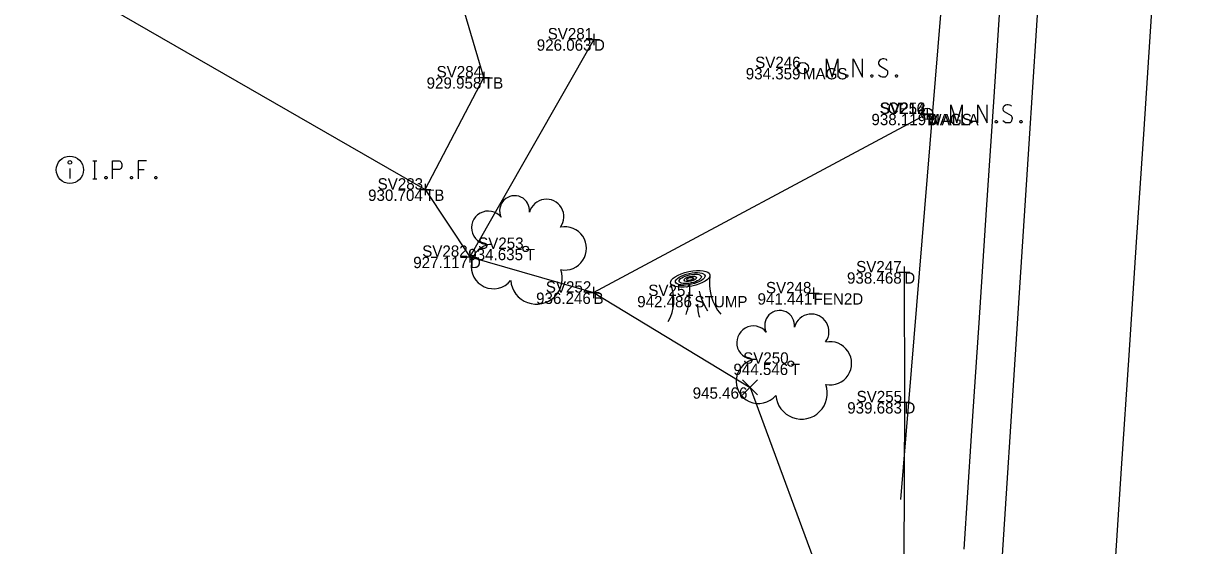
# Model space of a CAD drawing. Extents: x 1988835 to 1989144, y 657973 to 659339.
# Drawn here: x 1988889.6 to 1988993.8, y 658616.1 to 658662.1 of the extents above; entities that cross this region are included whole.
import ezdxf

# ---------------------------------------------------------------- set-up
doc = ezdxf.new("R2010")
doc.units = 0
for name, color, linetype in [('BR_X_SV_Abut_Text', 7, 'Continuous'), ('DR_X_Ditch', 7, 'Continuous'), ('DT_X_Terrain_Boundary', 7, 'Continuous'), ('PM_X_CL_Pass_Proh_Rt', 7, 'Continuous'), ('PV_X_EOP', 7, 'Continuous'), ('PV_X_Shoulder_Aggregate', 7, 'Continuous'), ('RD_X_Fence', 7, 'Continuous'), ('SV_P_Control_Cells_Set', 7, 'Continuous'), ('SV_X_Break_Lines', 7, 'Continuous'), ('SV_X_Mon_Cells_Found', 7, 'Continuous'), ('SV_X_Random_Point', 7, 'Continuous'), ('SV_X_Shot_Marker', 7, 'Continuous'), ('SV_X_Text_Comment', 7, 'Continuous'), ('SV_X_Top_of_Bank', 7, 'Continuous'), ('UT_X_Telecom', 7, 'Continuous'), ('UT_X_Telecom_Cells', 7, 'Continuous'), ('VG_X_Cells', 7, 'Continuous')]:
    doc.layers.add(name, color=color, linetype=linetype)

msp = doc.modelspace()

# ---------------------------------------------------------------- linework, layer by layer
at = {"layer": 'DR_X_Ditch'}
for points in [[(1988939.96, 658660.7), (1988929, 658641.52)], [(1988967.37, 658640.15), (1988967.38, 658628.69), (1988967.24, 658593.53)]]:
    msp.add_lwpolyline(points, dxfattribs=at)
at = {"layer": 'DT_X_Terrain_Boundary'}
msp.add_lwpolyline([(1988987.83, 658845.23), (1988984.81, 658799.59), (1988977.84, 658799.78), (1988968.83, 658798.91), (1988942.79, 658792.82), (1988927.35, 658779.11), (1988913.54, 658771.15), (1988908.13, 658758.46), (1988901.04, 658731.18), (1988897.02, 658728.69), (1988894.52, 658726.61), (1988891.03, 658722.22), (1988888.81, 658718.86), (1988886.03, 658711.78), (1988888.7, 658704.25), (1988881.58, 658703.53), (1988864.62, 658687.79), (1988839.99, 658661.75), (1988877.26, 658674.92), (1988925.04, 658647.45), (1988929, 658641.52), (1988939.92, 658638.36), (1988953.75, 658630), (1988967.24, 658593.53)], dxfattribs=at)
at = {"layer": 'PM_X_CL_Pass_Proh_Rt'}
msp.add_lwpolyline([(1988985.91, 658612.87), (1988986.57, 658622.85), (1988987.23, 658632.83), (1988987.89, 658642.8), (1988988.55, 658652.78), (1988989.21, 658662.76), (1988989.87, 658672.74), (1988990.52, 658682.72), (1988991.18, 658692.7), (1988991.84, 658702.67), (1988992.5, 658712.65), (1988993.16, 658722.63), (1988993.82, 658732.61), (1988994.48, 658742.59), (1988995.14, 658752.57), (1988995.8, 658762.54), (1988996.46, 658772.52), (1988997.12, 658782.5), (1988997.78, 658792.48), (1988998.44, 658802.46), (1988999.09, 658812.43), (1988999.75, 658822.41), (1989000.41, 658832.39), (1989001.07, 658842.37)], dxfattribs=at)
at = {"layer": 'PV_X_EOP'}
msp.add_lwpolyline([(1988990.64, 658841.1), (1988989.99, 658831.12), (1988989.35, 658821.14), (1988988.7, 658811.16), (1988988.06, 658801.18), (1988987.41, 658791.2), (1988986.77, 658781.22), (1988986.12, 658771.24), (1988985.47, 658761.26), (1988984.83, 658751.29), (1988984.18, 658741.31), (1988983.54, 658731.33), (1988982.89, 658721.35), (1988982.25, 658711.37), (1988981.6, 658701.39), (1988980.96, 658691.41), (1988980.31, 658681.43), (1988979.67, 658671.45), (1988979.02, 658661.47), (1988978.38, 658651.49), (1988977.73, 658641.51), (1988977.08, 658631.54), (1988976.44, 658621.56), (1988975.79, 658611.58)], dxfattribs=at)
at = {"layer": 'PV_X_Shoulder_Aggregate'}
msp.add_lwpolyline([(1988987.17, 658835.25), (1988986.51, 658825.27), (1988985.85, 658815.29), (1988985.19, 658805.31), (1988984.52, 658795.34), (1988983.86, 658785.36), (1988983.2, 658775.38), (1988982.54, 658765.4), (1988981.88, 658755.42), (1988981.22, 658745.44), (1988980.56, 658735.47), (1988979.9, 658725.49), (1988979.24, 658715.51), (1988978.58, 658705.53), (1988977.92, 658695.55), (1988977.25, 658685.58), (1988976.59, 658675.6), (1988975.93, 658665.62), (1988975.27, 658655.64), (1988974.61, 658645.66), (1988973.95, 658635.68), (1988973.29, 658625.71), (1988972.63, 658615.73)], dxfattribs=at)
at = {"layer": 'RD_X_Fence'}
msp.add_lwpolyline([(1988959.36, 658638.3), (1988959.36, 658638.3)], dxfattribs=at)
at = {"layer": 'SV_P_Control_Cells_Set'}
for points in [[(1988960.5, 658657.37), (1988960.5, 658658.97), (1988961, 658657.37), (1988961.49, 658658.97), (1988961.49, 658657.37)], [(1988962.87, 658657.37), (1988962.87, 658658.97), (1988963.69, 658657.37), (1988963.69, 658658.97)], [(1988965.84, 658658.85), (1988965.82, 658658.88), (1988965.79, 658658.91), (1988965.69, 658658.94), (1988965.57, 658658.97), (1988965.48, 658658.97), (1988965.45, 658658.97), (1988965.3, 658658.93), (1988965.18, 658658.85), (1988965.11, 658658.75), (1988965.08, 658658.65), (1988965.08, 658658.58), (1988965.11, 658658.48), (1988965.19, 658658.39), (1988965.8, 658658.01), (1988965.86, 658657.96), (1988965.88, 658657.91), (1988965.9, 658657.83), (1988965.9, 658657.76), (1988965.89, 658657.68), (1988965.88, 658657.63), (1988965.86, 658657.57), (1988965.83, 658657.52), (1988965.81, 658657.48), (1988965.78, 658657.44), (1988965.74, 658657.42), (1988965.7, 658657.39), (1988965.67, 658657.38), (1988965.57, 658657.37), (1988965.41, 658657.37), (1988965.31, 658657.39), (1988965.17, 658657.48), (1988965.08, 658657.56)], [(1988962.26, 658657.58), (1988962.32, 658657.58), (1988962.35, 658657.56), (1988962.38, 658657.51), (1988962.38, 658657.44), (1988962.35, 658657.39), (1988962.32, 658657.37), (1988962.26, 658657.37), (1988962.23, 658657.39), (1988962.2, 658657.44), (1988962.2, 658657.51), (1988962.23, 658657.56), (1988962.26, 658657.58)], [(1988964.48, 658657.58), (1988964.53, 658657.58), (1988964.57, 658657.56), (1988964.6, 658657.51), (1988964.6, 658657.44), (1988964.57, 658657.39), (1988964.53, 658657.37), (1988964.48, 658657.37), (1988964.44, 658657.39), (1988964.41, 658657.44), (1988964.41, 658657.51), (1988964.44, 658657.56), (1988964.48, 658657.58)], [(1988966.66, 658657.58), (1988966.71, 658657.58), (1988966.75, 658657.56), (1988966.78, 658657.51), (1988966.78, 658657.44), (1988966.75, 658657.39), (1988966.71, 658657.37), (1988966.66, 658657.37), (1988966.63, 658657.39), (1988966.59, 658657.44), (1988966.59, 658657.51), (1988966.63, 658657.56), (1988966.66, 658657.58)], [(1988971.49, 658653.33), (1988971.49, 658654.93), (1988972, 658653.33), (1988972.49, 658654.93), (1988972.49, 658653.33)], [(1988973.86, 658653.33), (1988973.86, 658654.93), (1988974.69, 658653.33), (1988974.69, 658654.93)], [(1988976.84, 658654.81), (1988976.82, 658654.84), (1988976.78, 658654.86), (1988976.69, 658654.9), (1988976.56, 658654.93), (1988976.48, 658654.93), (1988976.44, 658654.93), (1988976.3, 658654.89), (1988976.18, 658654.81), (1988976.1, 658654.71), (1988976.08, 658654.61), (1988976.08, 658654.53), (1988976.1, 658654.43), (1988976.19, 658654.35), (1988976.8, 658653.97), (1988976.85, 658653.92), (1988976.87, 658653.87), (1988976.89, 658653.79), (1988976.89, 658653.72), (1988976.88, 658653.64), (1988976.87, 658653.59), (1988976.85, 658653.53), (1988976.83, 658653.48), (1988976.81, 658653.44), (1988976.77, 658653.4), (1988976.74, 658653.38), (1988976.7, 658653.35), (1988976.66, 658653.34), (1988976.56, 658653.33), (1988976.41, 658653.33), (1988976.31, 658653.35), (1988976.17, 658653.44), (1988976.08, 658653.51)], [(1988973.26, 658653.54), (1988973.31, 658653.54), (1988973.35, 658653.51), (1988973.38, 658653.46), (1988973.38, 658653.4), (1988973.35, 658653.35), (1988973.31, 658653.33), (1988973.26, 658653.33), (1988973.22, 658653.35), (1988973.19, 658653.4), (1988973.19, 658653.46), (1988973.22, 658653.51), (1988973.26, 658653.54)], [(1988975.47, 658653.54), (1988975.53, 658653.54), (1988975.56, 658653.51), (1988975.59, 658653.46), (1988975.59, 658653.4), (1988975.56, 658653.35), (1988975.53, 658653.33), (1988975.47, 658653.33), (1988975.44, 658653.35), (1988975.41, 658653.4), (1988975.41, 658653.46), (1988975.44, 658653.51), (1988975.47, 658653.54)], [(1988977.66, 658653.54), (1988977.71, 658653.54), (1988977.74, 658653.51), (1988977.78, 658653.46), (1988977.78, 658653.4), (1988977.74, 658653.35), (1988977.71, 658653.33), (1988977.66, 658653.33), (1988977.62, 658653.35), (1988977.59, 658653.4), (1988977.59, 658653.46), (1988977.62, 658653.51), (1988977.66, 658653.54)]]:
    msp.add_lwpolyline(points, dxfattribs=at)
for centre in [(1988958.41, 658658.17), (1988969.4, 658654.13)]:
    msp.add_circle(centre, 0.497, dxfattribs=at)
at = {"layer": 'SV_X_Break_Lines'}
for points in [[(1988939.92, 658638.36), (1988969.4, 658654.13)], [(1988939.92, 658638.36), (1988939.92, 658638.36)]]:
    msp.add_lwpolyline(points, dxfattribs=at)
at = {"layer": 'SV_X_Mon_Cells_Found'}
msp.add_line((1988893.67, 658649.31), (1988893.67, 658648.43), dxfattribs=at)
for points in [[(1988895.7, 658649.99), (1988896.05, 658649.99)], [(1988895.87, 658648.39), (1988895.87, 658649.99)], [(1988897.44, 658648.39), (1988897.44, 658649.99), (1988897.97, 658649.99), (1988898.02, 658649.98), (1988898.1, 658649.96), (1988898.13, 658649.93), (1988898.17, 658649.9), (1988898.21, 658649.84), (1988898.24, 658649.78), (1988898.27, 658649.68), (1988898.27, 658649.53), (1988898.26, 658649.48), (1988898.23, 658649.4), (1988898.19, 658649.31), (1988898.15, 658649.27), (1988898.11, 658649.25), (1988898.06, 658649.22), (1988897.97, 658649.21), (1988897.44, 658649.21)], [(1988900.45, 658649.99), (1988899.69, 658649.99), (1988899.69, 658648.39)], [(1988896.83, 658648.61), (1988896.89, 658648.61), (1988896.92, 658648.58), (1988896.95, 658648.53), (1988896.95, 658648.47), (1988896.92, 658648.42), (1988896.89, 658648.39), (1988896.83, 658648.39), (1988896.8, 658648.42), (1988896.77, 658648.47), (1988896.77, 658648.53), (1988896.8, 658648.58), (1988896.83, 658648.61)], [(1988899.08, 658648.61), (1988899.14, 658648.61), (1988899.17, 658648.58), (1988899.2, 658648.53), (1988899.2, 658648.47), (1988899.17, 658648.42), (1988899.14, 658648.39), (1988899.08, 658648.39), (1988899.05, 658648.42), (1988899.02, 658648.47), (1988899.02, 658648.53), (1988899.05, 658648.58), (1988899.08, 658648.61)], [(1988899.69, 658649.21), (1988900.23, 658649.21)], [(1988901.23, 658648.61), (1988901.29, 658648.61), (1988901.32, 658648.58), (1988901.35, 658648.53), (1988901.35, 658648.47), (1988901.32, 658648.42), (1988901.29, 658648.39), (1988901.23, 658648.39), (1988901.2, 658648.42), (1988901.17, 658648.47), (1988901.17, 658648.53), (1988901.2, 658648.58), (1988901.23, 658648.61)], [(1988895.7, 658648.39), (1988896.05, 658648.39)]]:
    msp.add_lwpolyline(points, dxfattribs=at)
for centre, radius in [((1988893.67, 658649.19), 1.2), ((1988893.67, 658649.84), 0.16)]:
    msp.add_circle(centre, radius, dxfattribs=at)
at = {"layer": 'SV_X_Random_Point'}
for p, q in [((1988953.08, 658629.34), (1988954.41, 658630.67)), ((1988953.08, 658630.67), (1988954.41, 658629.34))]:
    msp.add_line(p, q, dxfattribs=at)
at = {"layer": 'SV_X_Shot_Marker'}
for p, q in [((1988939.96, 658661.2), (1988939.96, 658660.2)), ((1988939.46, 658660.7), (1988940.46, 658660.7)), ((1988939.96, 658660.7), (1988939.96, 658660.7)), ((1988929.74, 658657.35), (1988930.74, 658657.35)), ((1988930.24, 658657.85), (1988930.24, 658656.85)), ((1988930.24, 658657.35), (1988930.24, 658657.35)), ((1988968.9, 658654.13), (1988969.9, 658654.13)), ((1988968.9, 658654.13), (1988969.9, 658654.13)), ((1988969.4, 658654.63), (1988969.4, 658653.63)), ((1988969.4, 658654.63), (1988969.4, 658653.63)), ((1988969.4, 658654.13), (1988969.4, 658654.13)), ((1988969.4, 658654.13), (1988969.4, 658654.13)), ((1988925.04, 658647.95), (1988925.04, 658646.95)), ((1988924.54, 658647.45), (1988925.54, 658647.45)), ((1988925.04, 658647.45), (1988925.04, 658647.45)), ((1988928.5, 658641.52), (1988929.5, 658641.52)), ((1988929, 658642.02), (1988929, 658641.02)), ((1988929, 658641.52), (1988929, 658641.52)), ((1988967.37, 658640.65), (1988967.37, 658639.65)), ((1988966.87, 658640.15), (1988967.87, 658640.15)), ((1988967.37, 658640.15), (1988967.37, 658640.15)), ((1988939.42, 658638.36), (1988940.42, 658638.36)), ((1988939.92, 658638.86), (1988939.92, 658637.86)), ((1988939.92, 658638.36), (1988939.92, 658638.36)), ((1988958.86, 658638.3), (1988959.86, 658638.3)), ((1988959.36, 658638.8), (1988959.36, 658637.8)), ((1988959.36, 658638.3), (1988959.36, 658638.3)), ((1988967.38, 658629.19), (1988967.38, 658628.19)), ((1988966.88, 658628.69), (1988967.88, 658628.69)), ((1988967.38, 658628.69), (1988967.38, 658628.69))]:
    msp.add_line(p, q, dxfattribs=at)
at = {"layer": 'SV_X_Top_of_Bank'}
msp.add_lwpolyline([(1988925.04, 658647.45), (1988930.24, 658657.35), (1988925.34, 658673.89), (1988916.87, 658675.49), (1988894.86, 658691.24), (1988881.58, 658703.53)], dxfattribs=at)
at = {"layer": 'UT_X_Telecom'}
msp.add_lwpolyline([(1988967.08, 658620.12), (1988972.73, 658688.59), (1988973.99, 658703.44), (1988976, 658749.74), (1988978.85, 658805.85), (1988980.81, 658827.93)], dxfattribs=at)
at = {"layer": 'VG_X_Cells'}
msp.add_line((1988948.84, 658638.06), (1988948.84, 658638.06), dxfattribs=at)
for centre in [(1988933.93, 658642.22), (1988957.35, 658632.09)]:
    msp.add_circle(centre, 0.24, dxfattribs=at)
for centre, radius, start, end in [((1988932.95, 658645.59), 1.32, 354.0047, 205.9741), ((1988935.76, 658645.05), 1.55, 323.83, 165.0376), ((1988930.62, 658644.08), 1.47, 39.0625, 279.5412), ((1988937.39, 658642.26), 1.91, 259.1453, 101.4596), ((1988931.08, 658640.67), 1.97, 96.1722, 320.5737), ((1988934.88, 658639.62), 2.28, 184.9476, 19.4572), ((1988954.45, 658639.2), 4.29, 171.4106, 219.9194), ((1988943.01, 658637.71), 4, 331.5338, 20.9269), ((1988943.33, 658638.08), 5.05, 340.7938, 3.5481), ((1988955.35, 658640.12), 6.32, 194.9653, 212.1216), ((1988952.75, 658637.26), 3.64, 178.7926, 197.1224), ((1988956.36, 658635.46), 1.32, 354.0047, 205.9741), ((1988959.17, 658634.92), 1.55, 323.83, 165.0376), ((1988954.04, 658633.95), 1.47, 39.0625, 279.5412), ((1988960.81, 658632.12), 1.91, 259.1453, 101.4596), ((1988954.49, 658630.54), 1.97, 96.1722, 320.5737), ((1988958.29, 658629.48), 2.28, 184.9476, 19.4572)]:
    msp.add_arc(centre, radius, start, end, dxfattribs=at)
for major_axis in [(1.74, 0.37), (1.3, 0.28), (0.976, 0.211), (0.549, 0.119), (0.309, 0.067)]:
    msp.add_ellipse((1988948.47, 658639.57), major_axis=major_axis, ratio=0.36865, dxfattribs=at)

# ---------------------------------------------------------------- texts
at = {"layer": 'BR_X_SV_Abut_Text'}
for s, p in [('SV216', (1988965.19, 658654.13)), ('938.119', (1988964.47, 658653.13)), ('WALLA', (1988969.4, 658653.13))]:
    msp.add_text(s, height=1, dxfattribs=at).set_placement(p)
at = {"layer": 'SV_X_Text_Comment'}
for s, p in [('SV281', (1988935.87, 658660.7)), ('SV246', (1988954.2, 658658.17)), ('SV284', (1988926.06, 658657.35)), ('SV254', (1988965.23, 658654.13)), ('CP12', (1988965.9, 658654.13)), ('SV283', (1988920.85, 658647.45)), ('SV282', (1988924.79, 658641.52)), ('SV253', (1988929.73, 658642.22)), ('SV247', (1988963.12, 658640.15)), ('SV252', (1988935.71, 658638.36)), ('SV248', (1988955.15, 658638.3)), ('SV251', (1988944.76, 658638.06)), ('SV250', (1988953.14, 658632.09)), ('SV255', (1988963.16, 658628.69))]:
    msp.add_text(s, height=1, dxfattribs=at).set_placement(p)
at = {"layer": 'UT_X_Telecom'}
for s, p in [('D', (1988939.96, 658659.7)), ('MAGS', (1988958.41, 658657.17)), ('TB', (1988930.24, 658656.35)), ('MAGS', (1988969.4, 658653.13)), ('B', (1988969.4, 658653.13)), ('TB', (1988925.04, 658646.45)), ('D', (1988929, 658640.52)), ('T', (1988933.93, 658641.22)), ('D', (1988967.37, 658639.15)), ('B', (1988939.92, 658637.36)), ('FEN2D', (1988959.36, 658637.3)), ('STUMP', (1988948.84, 658637.06)), ('T', (1988957.35, 658631.09)), ('D', (1988967.38, 658627.69))]:
    msp.add_text(s, height=1, dxfattribs=at).set_placement(p)
at = {"layer": 'UT_X_Telecom_Cells'}
for s, p in [('926.063', (1988934.91, 658659.7)), ('934.359', (1988953.37, 658657.17)), ('929.958', (1988925.18, 658656.35)), ('938.119', (1988964.47, 658653.13)), ('938.119', (1988964.47, 658653.13)), ('930.704', (1988920.01, 658646.45)), ('927.117', (1988924, 658640.52)), ('934.635', (1988928.86, 658641.22)), ('938.468', (1988962.31, 658639.15)), ('936.246', (1988934.85, 658637.36)), ('941.441', (1988954.41, 658637.3)), ('942.486', (1988943.78, 658637.06)), ('944.546', (1988952.28, 658631.09)), ('945.466', (1988948.68, 658629)), ('939.683', (1988962.33, 658627.69))]:
    msp.add_text(s, height=1, dxfattribs=at).set_placement(p)

doc.saveas('drawing.dxf')
